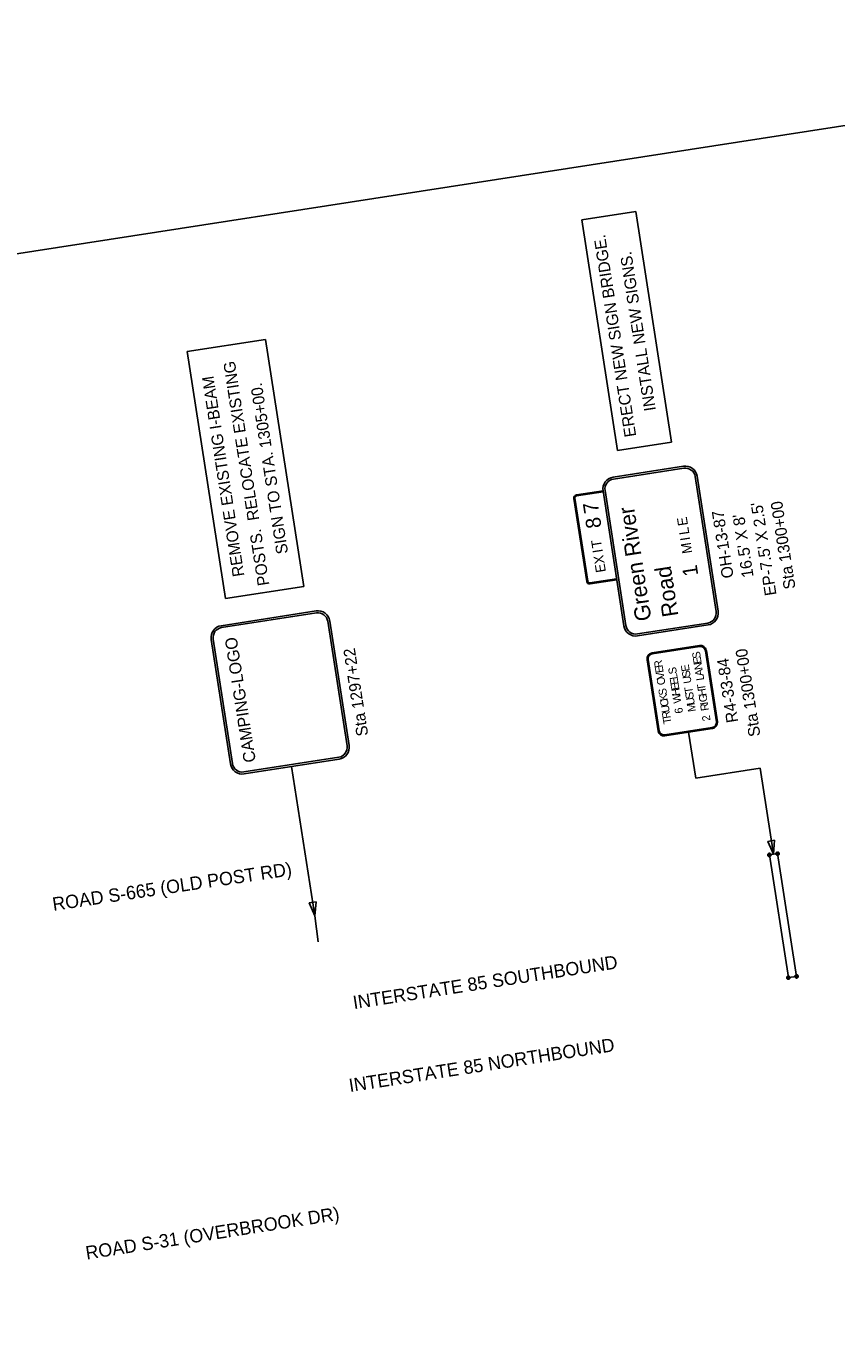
# Model space of a CAD drawing. Extents: x 1778251 to 1779871, y 1179849 to 1181087.
# Drawn here: x 1778856 to 1779342, y 1180288 to 1181067 of the extents above; entities that cross this region are included whole.
import ezdxf

# ---------------------------------------------------------------- set-up
doc = ezdxf.new("R2010")
doc.units = 0
for name, color, linetype in [('RD_EX_BldgApp', 7, 'Continuous'), ('RD_HC_Data', 7, 'Continuous'), ('RD_PD_PatLn1', 7, 'Continuous'), ('RD_TX_RoadID', 7, 'Continuous')]:
    doc.layers.add(name, color=color, linetype=linetype)

msp = doc.modelspace()

# ---------------------------------------------------------------- linework, layer by layer
at = {"layer": 'RD_EX_BldgApp'}
msp.add_line((1779031.39, 1180517.22), (1779029.41, 1180532.71), dxfattribs=at)
at = {"layer": 'RD_HC_Data'}
msp.add_lwpolyline([(1779870.61, 1180182.22), (1779733.69, 1181066.68), (1778251.34, 1180837.21), (1778404.33, 1179848.98), (1779093.19, 1179955.62), (1779077.13, 1180059.38)], close=True, dxfattribs=at)
at = {"layer": 'RD_PD_PatLn1'}
for p, q in [((1779189.59, 1180950.28), (1779222.01, 1180955.29)), ((1779222.01, 1180955.29), (1779243.42, 1180816.99)), ((1779211, 1180811.97), (1779189.59, 1180950.28)), ((1778952.89, 1180871.37), (1778999.95, 1180878.65)), ((1778999.95, 1180878.65), (1779022.9, 1180730.4)), ((1778975.84, 1180723.11), (1778952.89, 1180871.37)), ((1779243.42, 1180816.99), (1779211, 1180811.97)), ((1779022.9, 1180730.4), (1778975.84, 1180723.11)), ((1779253.76, 1180642.96), (1779258.04, 1180615.34)), ((1779015.53, 1180622.33), (1779029.41, 1180532.71)), ((1779296.68, 1180621.33), (1779258.04, 1180615.34)), ((1779296.68, 1180621.33), (1779304.67, 1180569.7)), ((1779303.03, 1180568.73), (1779301.41, 1180569.91)), ((1779302.81, 1180570.13), (1779301.63, 1180568.52)), ((1779307.12, 1180570.08), (1779302.22, 1180569.32)), ((1779302.22, 1180569.32), (1779313.62, 1180495.7)), ((1779307.92, 1180569.49), (1779306.31, 1180570.67)), ((1779307.71, 1180570.88), (1779306.53, 1180569.28)), ((1779318.51, 1180496.46), (1779307.12, 1180570.08)), ((1779031.39, 1180517.22), (1779029.41, 1180532.71)), ((1779314.42, 1180495.11), (1779312.81, 1180496.29)), ((1779314.21, 1180496.5), (1779313.03, 1180494.89)), ((1779313.62, 1180495.7), (1779318.51, 1180496.46)), ((1779319.32, 1180495.87), (1779317.71, 1180497.05)), ((1779319.1, 1180497.26), (1779317.93, 1180495.65))]:
    msp.add_line(p, q, dxfattribs=at)
for points in [[(1779208.43, 1180795.99), (1779250.7, 1180802.54)], [(1779208.61, 1180794.81), (1779250.88, 1180801.35)], [(1779257.73, 1180796.34), (1779270.27, 1180715.32)], [(1779258.92, 1180796.53), (1779271.46, 1180715.5)], [(1779192.61, 1180733.44), (1779184.9, 1180783.25)], [(1779185.49, 1180783.34), (1779193.2, 1180733.53)], [(1779186.4, 1180785.3), (1779202.41, 1180787.78), (1779202.5, 1180787.19)], [(1779202.5, 1180787.19), (1779186.49, 1180784.71)], [(1779214.96, 1180706.75), (1779202.41, 1180787.78)], [(1779216.14, 1180706.94), (1779203.6, 1180787.96)], [(1779194.57, 1180732.53), (1779210.58, 1180735.01), (1779210.67, 1180734.41), (1779194.66, 1180731.94)], [(1778973.3, 1180706.86), (1779030.23, 1180715.68)], [(1778973.49, 1180705.68), (1779030.41, 1180714.49)], [(1779037.26, 1180709.48), (1779048.82, 1180634.77)], [(1779038.44, 1180709.66), (1779050.01, 1180634.95)], [(1779265.26, 1180708.47), (1779222.99, 1180701.92)], [(1779265.45, 1180707.28), (1779223.17, 1180700.74)], [(1778978.86, 1180623.94), (1778967.29, 1180698.65)], [(1778980.04, 1180624.12), (1778968.48, 1180698.83)], [(1779260.28, 1180694.97), (1779231.82, 1180690.56)], [(1779231.91, 1180689.97), (1779260.37, 1180694.37)], [(1779263.8, 1180691.87), (1779270.41, 1180649.18)], [(1779271, 1180649.27), (1779264.39, 1180691.96)], [(1779228.81, 1180686.45), (1779235.42, 1180643.76)], [(1779236.01, 1180643.85), (1779229.41, 1180686.54)], [(1779267.9, 1180645.75), (1779239.44, 1180641.35)], [(1779239.53, 1180640.75), (1779267.99, 1180645.16)], [(1779043.81, 1180627.92), (1778986.89, 1180619.11)], [(1779044, 1180626.74), (1778987.07, 1180617.92)], [(1779302.37, 1180568.33), (1779302.21, 1180568.32), (1779302.04, 1180568.34), (1779301.88, 1180568.38), (1779301.73, 1180568.45), (1779301.59, 1180568.55), (1779301.47, 1180568.66), (1779301.37, 1180568.79), (1779301.29, 1180568.94), (1779301.24, 1180569.1), (1779301.22, 1180569.27), (1779301.23, 1180569.44), (1779301.26, 1180569.6), (1779301.32, 1180569.76), (1779301.4, 1180569.9), (1779301.51, 1180570.03), (1779301.64, 1180570.13), (1779301.78, 1180570.22), (1779301.94, 1180570.28), (1779302.07, 1180570.31)], [(1779302.07, 1180570.31), (1779302.23, 1180570.32), (1779302.4, 1180570.31), (1779302.56, 1180570.26), (1779302.71, 1180570.19), (1779302.85, 1180570.1), (1779302.97, 1180569.98), (1779303.07, 1180569.85), (1779303.15, 1180569.7), (1779303.2, 1180569.54), (1779303.22, 1180569.37), (1779303.21, 1180569.21), (1779303.18, 1180569.04), (1779303.12, 1180568.89), (1779303.04, 1180568.74), (1779302.93, 1180568.62), (1779302.8, 1180568.51), (1779302.66, 1180568.42), (1779302.5, 1180568.36), (1779302.37, 1180568.33)], [(1779307.27, 1180569.09), (1779307.1, 1180569.08), (1779306.94, 1180569.1), (1779306.78, 1180569.14), (1779306.62, 1180569.21), (1779306.49, 1180569.3), (1779306.37, 1180569.42), (1779306.27, 1180569.55), (1779306.19, 1180569.7), (1779306.14, 1180569.86), (1779306.12, 1180570.03), (1779306.12, 1180570.19), (1779306.16, 1180570.36), (1779306.22, 1180570.51), (1779306.3, 1180570.66), (1779306.41, 1180570.79), (1779306.54, 1180570.89), (1779306.68, 1180570.98), (1779306.83, 1180571.04), (1779306.97, 1180571.07)], [(1779306.97, 1180571.07), (1779307.13, 1180571.08), (1779307.3, 1180571.06), (1779307.46, 1180571.02), (1779307.61, 1180570.95), (1779307.75, 1180570.86), (1779307.87, 1180570.74), (1779307.97, 1180570.61), (1779308.04, 1180570.46), (1779308.09, 1180570.3), (1779308.12, 1180570.13), (1779308.11, 1180569.97), (1779308.08, 1180569.8), (1779308.02, 1180569.65), (1779307.93, 1180569.5), (1779307.83, 1180569.37), (1779307.7, 1180569.27), (1779307.56, 1180569.18), (1779307.4, 1180569.12), (1779307.27, 1180569.09)], [(1779313.77, 1180494.71), (1779313.6, 1180494.7), (1779313.44, 1180494.71), (1779313.28, 1180494.76), (1779313.12, 1180494.83), (1779312.99, 1180494.92), (1779312.87, 1180495.04), (1779312.77, 1180495.17), (1779312.69, 1180495.32), (1779312.64, 1180495.48), (1779312.62, 1180495.65), (1779312.62, 1180495.81), (1779312.66, 1180495.98), (1779312.72, 1180496.13), (1779312.8, 1180496.28), (1779312.91, 1180496.4), (1779313.04, 1180496.51), (1779313.18, 1180496.6), (1779313.33, 1180496.66), (1779313.47, 1180496.69)], [(1779313.47, 1180496.69), (1779313.63, 1180496.7), (1779313.8, 1180496.68), (1779313.96, 1180496.64), (1779314.11, 1180496.57), (1779314.25, 1180496.47), (1779314.37, 1180496.36), (1779314.47, 1180496.23), (1779314.54, 1180496.08), (1779314.59, 1180495.92), (1779314.62, 1180495.75), (1779314.61, 1180495.58), (1779314.58, 1180495.42), (1779314.52, 1180495.26), (1779314.43, 1180495.12), (1779314.33, 1180494.99), (1779314.2, 1180494.89), (1779314.06, 1180494.8), (1779313.9, 1180494.74), (1779313.77, 1180494.71)], [(1779318.67, 1180495.47), (1779318.5, 1180495.46), (1779318.33, 1180495.47), (1779318.17, 1180495.52), (1779318.02, 1180495.59), (1779317.88, 1180495.68), (1779317.76, 1180495.8), (1779317.66, 1180495.93), (1779317.59, 1180496.08), (1779317.54, 1180496.24), (1779317.52, 1180496.4), (1779317.52, 1180496.57), (1779317.55, 1180496.73), (1779317.61, 1180496.89), (1779317.7, 1180497.03), (1779317.81, 1180497.16), (1779317.93, 1180497.27), (1779318.08, 1180497.36), (1779318.23, 1180497.42), (1779318.36, 1180497.45)], [(1779318.36, 1180497.45), (1779318.53, 1180497.46), (1779318.7, 1180497.44), (1779318.86, 1180497.4), (1779319.01, 1180497.33), (1779319.15, 1180497.23), (1779319.27, 1180497.12), (1779319.37, 1180496.98), (1779319.44, 1180496.83), (1779319.49, 1180496.67), (1779319.51, 1180496.51), (1779319.51, 1180496.34), (1779319.48, 1180496.18), (1779319.42, 1180496.02), (1779319.33, 1180495.88), (1779319.22, 1180495.75), (1779319.1, 1180495.64), (1779318.95, 1180495.56), (1779318.8, 1180495.5), (1779318.67, 1180495.47)]]:
    msp.add_lwpolyline(points, dxfattribs=at)
for points in [[(1779305.34, 1180578.13), (1779304.67, 1180569.7), (1779301.3, 1180577.46)], [(1779030.18, 1180541.13), (1779029.41, 1180532.71), (1779026.13, 1180540.5)]]:
    msp.add_lwpolyline(points, close=True, dxfattribs=at)
for centre, radius, start, end in [((1779251.8, 1180795.42), 7.2, 8.80001, 98.80001), ((1779251.8, 1180795.42), 6, 8.80001, 98.80001), ((1779209.53, 1180788.88), 7.2, 98.80001, 188.80001), ((1779209.53, 1180788.88), 6, 98.80001, 188.80001), ((1779186.68, 1180783.52), 1.8, 98.80001, 188.80001), ((1779186.68, 1180783.52), 1.2, 98.80001, 188.80001), ((1779194.39, 1180733.71), 1.8, 188.80001, 278.80001), ((1779194.39, 1180733.71), 1.2, 188.80001, 278.80001), ((1779031.33, 1180708.56), 7.2, 8.80001, 98.80001), ((1779031.33, 1180708.56), 6, 8.80001, 98.80001), ((1779264.34, 1180714.4), 6, 278.80001, 8.80001), ((1779264.34, 1180714.4), 7.2, 278.80001, 8.80001), ((1778974.41, 1180699.75), 7.2, 98.80001, 188.80001), ((1778974.41, 1180699.75), 6, 98.80001, 188.80001), ((1779222.07, 1180707.85), 7.2, 188.80001, 278.80001), ((1779222.07, 1180707.85), 6, 188.80001, 278.80001), ((1779232.37, 1180687), 3.6, 98.80001, 188.80001), ((1779232.37, 1180687), 3, 98.80001, 188.80001), ((1779260.83, 1180691.41), 3.6, 8.80001, 98.80001), ((1779260.83, 1180691.41), 3, 8.80001, 98.80001), ((1779238.98, 1180644.31), 3.6, 188.80001, 278.80001), ((1779238.98, 1180644.31), 3, 188.80001, 278.80001), ((1779267.44, 1180648.72), 3, 278.80001, 8.80001), ((1779267.44, 1180648.72), 3.6, 278.80001, 8.80001), ((1779042.89, 1180633.85), 6, 278.80001, 8.80001), ((1779042.89, 1180633.85), 7.2, 278.80001, 8.80001), ((1778985.97, 1180625.04), 7.2, 188.80001, 278.80001), ((1778985.97, 1180625.04), 6, 188.80001, 278.80001)]:
    msp.add_arc(centre, radius, start, end, dxfattribs=at)

# ---------------------------------------------------------------- texts
for s, height, rotation, p in [('ERECT NEW SIGN BRIDGE.', 6.9998, 98.80009, (1779222.36, 1180820.59)), ('INSTALL NEW SIGNS.', 6.9998, 98.80009, (1779234.12, 1180836.16)), ('POSTS.  RELOCATE EXISTING', 6.9998, 98.80009, (1779002.25, 1180731.37)), ('REMOVE EXISTING I-BEAM', 6.9998, 98.80009, (1778987.24, 1180736.81)), ('SIGN TO STA. 1305+00.', 6.9998, 98.80009, (1779013.47, 1180750.41)), ('7', 9, 98.80001, (1779200.15, 1180774.94)), ('Green River', 9.6, 98.80001, (1779231.53, 1180710.38)), ("EP-7.5' X 2.5'", 7, 98.80009, (1779306.53, 1180725.4)), ('Sta 1300+00', 7, 98.80009, (1779317.97, 1180729.29)), ('8', 9, 98.80001, (1779201.54, 1180765.94)), ('E', 6, 98.80001, (1779253.43, 1180767.24)), ('OH-13-87', 7, 98.80009, (1779280.83, 1180735.87)), ("16.5' X 8'", 7, 98.80009, (1779292.8, 1180736.28)), ('L', 6, 98.80001, (1779254.26, 1180761.88)), ('I', 6, 98.80001, (1779254.81, 1180758.33)), ('T', 6, 98.80001, (1779201.88, 1180753.98)), ('I', 6, 98.80001, (1779202.33, 1180751.03)), ('M', 6, 98.80001, (1779256.01, 1180750.56)), ('X', 6, 98.80001, (1779203.37, 1180744.3)), ('E', 6, 98.80001, (1779204.16, 1180739.21)), ('Road', 9.6, 98.80001, (1779247.66, 1180712.87)), ('1', 9, 98.80001, (1779259.6, 1180737.21)), ('CAMPING-LOGO', 7.2, 98.80001, (1778994.12, 1180625.36)), ('Sta 1297+22', 7, 98.80009, (1779061.57, 1180641.13)), ('S', 4.8, 98.80001, (1779261.14, 1180687.47)), ('Sta 1300+00', 7, 98.80009, (1779296.87, 1180640.83)), ('R', 4.8, 98.80001, (1779238.31, 1180681.99)), ('E', 4.8, 98.80001, (1779238.8, 1180678.82)), ('S', 4.8, 98.80001, (1779246.8, 1180678.14)), ('E', 4.8, 98.80001, (1779254.44, 1180679.73)), ('E', 4.8, 98.80001, (1779261.63, 1180684.3)), ('N', 4.8, 98.80001, (1779262.19, 1180680.7)), ('R4-33-84', 7, 98.80009, (1779283.53, 1180649.19)), ('V', 4.8, 98.80001, (1779239.37, 1180675.13)), ('O', 4.8, 98.80001, (1779239.92, 1180671.59)), ('L', 4.8, 98.80001, (1779247.29, 1180674.97)), ('E', 4.8, 98.80001, (1779247.78, 1180671.8)), ('S', 4.8, 98.80001, (1779255, 1180676.13)), ('U', 4.8, 98.80001, (1779255.56, 1180672.54)), ('A', 4.8, 98.80001, (1779262.77, 1180676.94)), ('L', 4.8, 98.80001, (1779263.18, 1180674.3)), ('S', 4.8, 98.80001, (1779240.87, 1180665.43)), ('E', 4.8, 98.80001, (1779248.27, 1180668.62)), ('H', 4.8, 98.80001, (1779248.83, 1180665.03)), ('T', 4.8, 98.80001, (1779256.47, 1180666.61)), ('S', 4.8, 98.80001, (1779257, 1180663.22)), ('T', 4.8, 98.80001, (1779264.09, 1180668.37)), ('H', 4.8, 98.80001, (1779264.62, 1180664.97)), ('K', 4.8, 98.80001, (1779241.4, 1180662.04)), ('C', 4.8, 98.80001, (1779241.92, 1180658.64)), ('U', 4.8, 98.80001, (1779242.48, 1180655.05)), ('W', 4.8, 98.80001, (1779249.5, 1180660.67)), ('U', 4.8, 98.80001, (1779257.56, 1180659.62)), ('M', 4.8, 98.80001, (1779258.19, 1180655.55)), ('G', 4.8, 98.80001, (1779265.18, 1180661.38)), ('I', 4.8, 98.80001, (1779265.43, 1180659.71)), ('R', 4.8, 98.80001, (1779265.99, 1180656.12)), ('R', 4.8, 98.80001, (1779243.03, 1180651.46)), ('T', 4.8, 98.80001, (1779243.53, 1180648.28)), ('6', 4.8, 98.80001, (1779250.45, 1180654.52)), ('2', 4.8, 98.80001, (1779266.94, 1180649.97))]:
    msp.add_text(s, height=height, rotation=rotation, dxfattribs=at).set_placement(p)
at = {"layer": 'RD_TX_RoadID'}
for s, rotation, p in [('ROAD S-665 (OLD POST RD)', 8.46568, (1778872.65, 1180535.76)), ('INTERSTATE 85 SOUTHBOUND', 8.80001, (1779052.99, 1180476.75)), ('INTERSTATE 85 NORTHBOUND', 8.80001, (1779050.58, 1180427)), ('ROAD S-31 (OVERBROOK DR)', 8.91152, (1778892.6, 1180326.51))]:
    msp.add_text(s, height=8, rotation=rotation, dxfattribs=at).set_placement(p)

doc.saveas('drawing.dxf')
